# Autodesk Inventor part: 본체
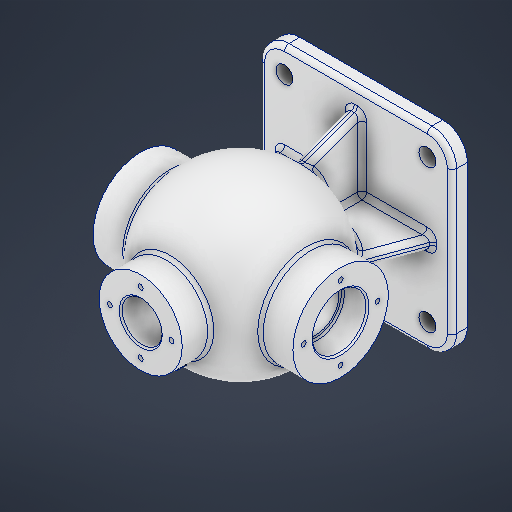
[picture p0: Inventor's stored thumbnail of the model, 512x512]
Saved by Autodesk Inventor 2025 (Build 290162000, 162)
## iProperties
Created: 2025-08
Part Number: 본체
Material: 알루미늄 6061
Document SubType Name: Modeling
Designer: infra11
Density: 2.7 g/cm^3
Appearance: 알루미늄 - 평지
Mass: 1519.11 g
Surface Area: 1171.84 cm^2
Volume: 562.634 cm^3
Author: infra11
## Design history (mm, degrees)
sketch "스케치1"
  geometry: L1 (62.5, -62.5)-(-62.5, -62.5); L2 (-62.5, -62.5)-(-62.5, 62.5); L3 (-62.5, 62.5)-(62.5, 62.5); L4 (62.5, 62.5)-(62.5, -62.5); L5 (62.5, -62.5)-(-62.5, 62.5); L6 (-62.5, -62.5)-(62.5, 62.5); 1 further point
  constraints: 12 end point, 2 midpoint, 2 parallel, 1 horizontal, 1 perpendicular
  dimensions: "d0" = 125 distance of L2.end L3.end; "d1" = 125 distance of L1.end L2.end
extrude "돌출1" new body sketch "스케치1" distance "d2" = 10; taper "d3" = 0 deg
sketch "스케치3"
  geometry: L1 (0, 139)-(0, 31); L2 (-62.5, 0)-(62.5, 0) reference; C1 r 44 at (0, 85); A1 r 54 centre (0, 85) between (0, 139) and (0, 31); 4 further points
  constraints: 2 centre point, 2 coincident, 2 end point, 2 point on circle, 1 midpoint, 1 vertical
  dimensions: "d4" = 85 distance from line of L2 point (0, 85); "d5" = 108 diameter of A1; "d6" = 62.5 distance from line of L2.end L1; "d22" = 88 diameter of C1
revolve "회전1" stored, may be unused: angle "d7" = 90 deg
sketch "스케치4"
  geometry: L1 (62.5, 10)-(-62.5, 10) reference; L2 (-50.5, 10)-(-33.792, 55.905); L3 (50.5, 10)-(33.792, 55.905); L4 (-62.5, 0)-(-62.5, 10) reference; L5 (62.5, 0)-(62.5, 10) reference; L6 (-33.792, 55.905)-(33.792, 55.905); 1 further point
  constraints: 6 end point, 2 point on line, 1 equal length
  dimensions: "d8" = 12 distance from line of L4 L2.start; "d9" = 12 distance from line of L5 L3.start; "d10" = 70 deg angle of L1 L2; "d11" = 70 deg angle of L1 L3; "d12" = 67.584 distance of L2.end L3.end
extrude "돌출2" join sketch "스케치4" stored distance "d13" = 8; taper "d14" = 0 deg
sketch "스케치5"
  geometry: L1 (-50.5, 10)-(-32.017, 60.783); L2 (62.5, 10)-(-62.5, 10) reference; L3 (50.5, 10)-(32.017, 60.783); L4 (-62.5, 0)-(-62.5, 10) reference; L5 (62.5, 0)-(62.5, 10) reference; L6 (-32.017, 60.783)-(-4, 60.783); L7 (-4, 60.783)-(-4, 46.186); L8 (32.017, 60.783)-(4, 60.783); L9 (4, 60.783)-(4, 46.186); 2 further points; 1 other entity
  constraints: 12 end point, 3 point on line, 2 perpendicular, 1 equal length, 1 horizontal, 1 other
  dimensions: "d15" = 12 distance from line of L4 L1.start; "d16" = 12 distance from line of L3.start L5; "d17" = 70 deg angle of L2 L1; "d18" = 70 deg angle of L2 L3; "d19" = 28.01666 distance of L1.end L6.end
extrude "돌출3" join sketch "스케치5" stored distance "d20" = 8; taper "d21" = 0 deg
sketch "스케치6"
  geometry: L1 (-65, 54)-(65, 54); L2 (65, 54)-(65, 116); L3 (65, 116)-(-65, 116); L4 (-65, 116)-(-65, 54); L5 (-65, 54)-(65, 116); L6 (65, 54)-(-65, 116); L7 (-62.5, 0)-(62.5, 0) reference; L8 (65, 85)-(-65, 85); L9 (65, 85)-(49, 85); L10 (49, 85)-(49, 102.5); L11 (49, 102.5)-(65, 102.5); L12 (65, 102.5)-(65, 85); L13 (27, 150)-(-27, 150); L14 (-27, 150)-(-27, 131.765); L15 (-27, 131.765)-(27, 131.765); L16 (27, 131.765)-(27, 150); L17 (0, 150)-(0, 131.765); L18 (-49, 102.5)-(-65, 102.5); L19 (-49, 85)-(-49, 102.5); A1 r 54 centre (0, 85) between (37.385, 46.034) and (-37.385, 46.034) reference; 15 further points
  constraints: 36 end point, 6 midpoint, 6 parallel, 3 horizontal, 3 perpendicular, 3 symmetric about line, 2 point on circle, 2 vertical alignment, 1 vertical
  dimensions: "d23" = 130 distance of L3.end L2.end; "d24" = 62 distance of L2.end L1.end; "d25" = 85 distance from line of L7 point (0, 85); "d26" = 16 distance of L10.end L11.end; "d27" = 17.5 distance of L9.end L10.end; "d28" = 150 distance between parallel lines of L7 L13; "d29" = 54 distance between parallel lines of L14 L16
revolve "회전2" stored, may be unused: angle "d30" = 90 deg
revolve "회전3" stored, may be unused: angle "d31" = 90 deg
sketch "스케치7"
  geometry: C1 r 17.5 at (0, 0) reference; 2 further points
  constraints: 1 coincident
hole "구멍1" sketch "스케치7" at (0, 0) diameter "d32" = 30; stored, may be unused: countersink angle "d36" = 90 deg, drill point angle "d38" = 0 deg; dims "d33" = 12, "d34" = 10, "d35" = 1, "d37" = 17.1
sketch "스케치8"
  geometry: 2 further points
  constraints: 1 coincident
hole "구멍2" sketch "스케치8" at (0, 0) diameter "d39" = 26; stored, may be unused: countersink angle "d43" = 90 deg, drill point angle "d45" = 0 deg; dims "d40" = 6, "d41" = 4, "d42" = 2, "d44" = 8
revolve "회전4" stored, may be unused: angle "d46" = 90 deg
sketch "스케치9"
  geometry: L1 (-37.329, -4)-(-4, -4) reference; A1 r 20 centre (0, 0) between (0, -20) and (-20, 0); 2 further points
  constraints: 4 point on circle, 1 centre point
  dimensions: "d100" = 40 diameter of A1; "d101" = 4 distance from line of point (20, 0) L1; "d102" = 24 distance from line of point (0, 20) L1; "d103" = 4 distance from line of A1.centre L1; "d104" = 16 distance from line of A1.start L1; "d105" = 4 distance from line of A1.end L1; "d106" = 24.33105 distance of L1.end point (20, 0)
hole "구멍3" sketch "스케치9" at (0, -20), (-20, 0), (0, 20), (20, 0) diameter "d51" = 3.242; stored, may be unused: countersink angle "d55" = 90 deg, drill point angle "d57" = 118 deg; dims "d52" = 9, "d53" = 4, "d54" = 2, "d56" = 11
sketch "스케치10"
  geometry: L1 (85, -62.5)-(85, 62.5) reference; A1 r 24 centre (0, 0) between (0, -24) and (-24, 0); 3 further points
  constraints: 4 point on circle, 3 horizontal alignment, 2 vertical alignment, 1 centre point
  dimensions: "d58" = 48 diameter of A1; "d59" = 85 distance from line of L1 A1.centre
hole "구멍4" sketch "스케치10" at (0, -24), (-24, 0), (0, 24), (24, 0) diameter "d60" = 3.242; stored, may be unused: countersink angle "d64" = 90 deg, drill point angle "d66" = 118 deg; dims "d61" = 12, "d62" = 4, "d63" = 2, "d65" = 15
node "작업 평면1"
sketch "스케치11" dims "d0" = 125, "d1" = 125
  geometry: L1 (-20.739, 144.002)-(20.739, 144.002); L2 (20.739, 144.002)-(20.739, 137.998); L3 (20.739, 137.998)-(-20.739, 137.998); L4 (-20.739, 137.998)-(-20.739, 144.002); L5 (-62.5, 10)-(62.5, 10) reference; L6 (-27, 150)-(27, 150) reference; 4 further points
  constraints: 3 midpoint, 1 vertical alignment, 2 other
  dimensions: "d68" = 9 distance from line of point (-20.739, 141) L6
feature "엠보싱1" sketch "스케치11" dims "d0" = 125, "d1" = 125, "d69" = 0.5, "d70" = 0
sketch "스케치12"
  geometry: L1 (46.5, -46.5)-(-46.5, -46.5); L2 (-46.5, -46.5)-(-46.5, 46.5); L3 (-46.5, 46.5)-(46.5, 46.5); L4 (46.5, 46.5)-(46.5, -46.5); L5 (46.5, -46.5)-(-46.5, 46.5); L6 (-46.5, -46.5)-(46.5, 46.5); 1 further point
  constraints: 12 end point, 2 midpoint, 2 parallel, 1 horizontal, 1 perpendicular
  dimensions: "d71" = 93 distance of L2.end L3.end; "d72" = 93 distance of L1.end L2.end
hole "구멍5" sketch "스케치12" at (-46.5, -46.5), (46.5, -46.5), (-46.5, 46.5), (46.5, 46.5) diameter "d73" = 11; stored, may be unused: countersink angle "d77" = 90 deg, drill point angle "d79" = 0 deg; dims "d74" = 12, "d75" = 4, "d76" = 2, "d78" = 15
fillet "모깎기1" dims "d80" = 3
fillet "모깎기2" dims "d81" = 3
fillet "모깎기3" dims "d82" = 3
fillet "모깎기4" dims "d83" = 16
fillet "모깎기5" dims "d84" = 3
chamfer "모따기1" distance "d85" = 1; stored, may be unused: second distance "d86" = 2, angle "d87" = 45 deg
chamfer "모따기2" distance "d88" = 1; stored, may be unused: second distance "d89" = 2, angle "d90" = 45 deg
chamfer "모따기5" distance "d97" = 1; stored, may be unused: second distance "d98" = 2, angle "d99" = 45 deg
revolve "회전5" stored, may be unused: angle "d107" = 90 deg
chamfer "모따기6" distance "d108" = 1; stored, may be unused: second distance "d109" = 2, angle "d110" = 45 deg
chamfer "모따기7" distance "d111" = 1; stored, may be unused: second distance "d112" = 2, angle "d113" = 45 deg
feature "Ϊ耀ά耀ή耀ΰ耀β耀δ耀ζ耀θ耀" dims "d0" = 125, "d1" = 125, "d2" = 10, "d3" = 0, "d4" = 85, "d5" = 108, "d6" = 62.5, "d7" = 90 deg, "d8" = 12, "d9" = 12, "d10" = 70 deg, "d11" = 70 deg, "d12" = 67.584, "d13" = 8, "d14" = 0, "d15" = 12, "d16" = 12, "d17" = 70 deg, "d18" = 70 deg, "d19" = 28.01666, "d20" = 8, "d21" = 0, "d22" = 88, "d23" = 130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
node "솔리드1"
mirror "미러1"
feature "A9D066F2-1C7D-4E18-AEED-F7BC21143FA4" dims "d32" = 30, "d33" = 12, "d34" = 10, "d35" = 1, "d36" = 90 deg, "d37" = 17.1, "d38" = 0
